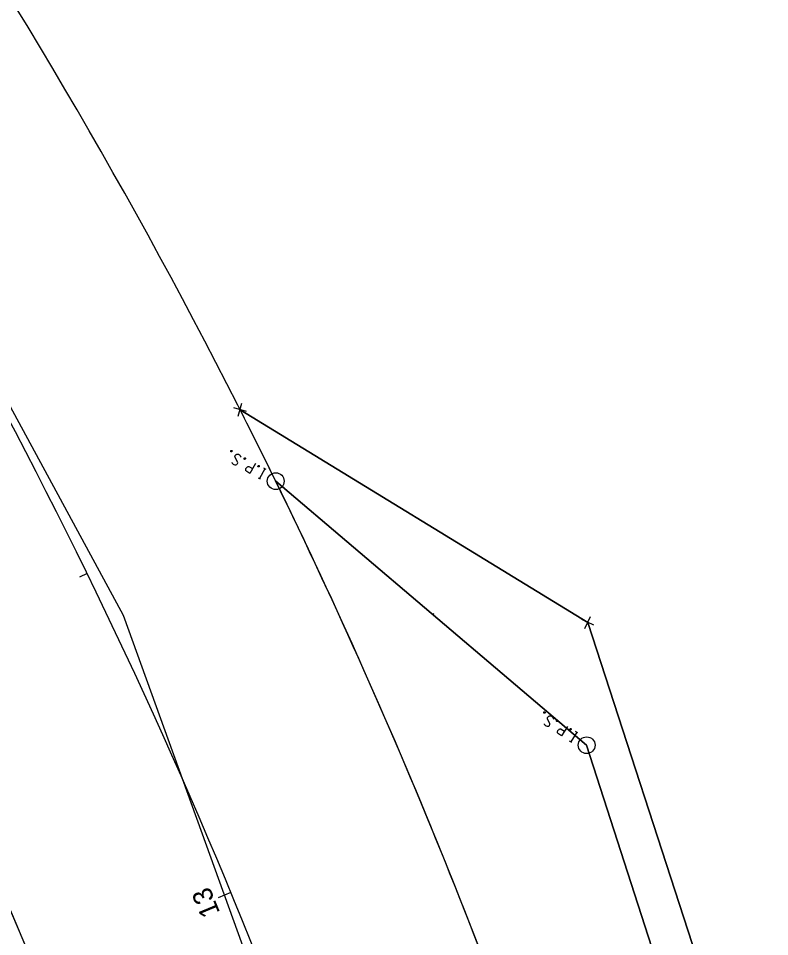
# Model space of a CAD drawing. Extents: x 2392034 to 2394211, y 184331 to 186655.
# Drawn here: x 2392791 to 2392898.3, y 185380.6 to 185511.7 of the extents above; entities that cross this region are included whole.
import ezdxf

# ---------------------------------------------------------------- set-up
doc = ezdxf.new("R2010")
doc.units = 0
for name, color, linetype in [('V-ROAD-SIGN', 7, 'Continuous'), ('V-SITE-MAIL', 7, 'Continuous'), ('V-SURV-ANNO', 7, 'Continuous'), ('V-TOPO-ANNO', 7, 'Continuous'), ('V-TOPO-TINN', 7, 'Continuous'), ('V-TOPO-USER', 7, 'Continuous'), ('V-TOPO-WSHD', 7, 'Continuous'), ('V-UTIL-NGAS-STRC', 7, 'Continuous'), ('V-UTIL-SSWR-STRC', 7, 'Continuous'), ('V-UTIL-STRM-STRC', 7, 'Continuous')]:
    doc.layers.add(name, color=color, linetype=linetype)

msp = doc.modelspace()

# ---------------------------------------------------------------- linework, layer by layer
at = {"layer": 'Defpoints'}
msp.add_circle((2392850.29, 185426.65), 0.05, dxfattribs=at)
at = {"layer": 'V-ROAD-SIGN'}
for radius, end in [(830, 45.41914), (770, 44.49359)]:
    msp.add_arc((2392082.2, 185080.9), radius, 15.02013, end, dxfattribs=at)
at = {"layer": 'V-SITE-MAIL'}
msp.add_arc((2392082.2, 185080.9), 800, 15.02013, 44.49359, dxfattribs=at)
at = {"layer": 'V-SURV-ANNO'}
for p, q in [((2392800.83, 185432.43), (2392799.75, 185431.91)), ((2392821.38, 185386.86), (2392819.54, 185386.1))]:
    msp.add_line(p, q, dxfattribs=at)
at = {"layer": 'V-TOPO-ANNO'}
for p, q in [((2392806.01, 185426.43), (2392759.81, 185511.73)), ((2392806.01, 185426.43), (2392759.81, 185511.73)), ((2392843.3, 185323.45), (2392806.01, 185426.43)), ((2392843.3, 185323.45), (2392806.01, 185426.43))]:
    msp.add_line(p, q, dxfattribs=at)
at = {"layer": 'V-TOPO-TINN'}
for points in [[(2392821.42, 185449.8), (2392821.38, 185449.82), (2392821.36, 185449.86), (2392821.35, 185449.92), (2392821.38, 185449.98), (2392821.44, 185450), (2392821.48, 185450.01), (2392821.53, 185449.98), (2392821.54, 185449.95), (2392821.55, 185449.89), (2392821.52, 185449.83), (2392821.46, 185449.8), (2392821.42, 185449.8)], [(2392821.52, 185448.29), (2392821.53, 185448.26), (2392821.55, 185448.22), (2392821.61, 185448.14), (2392821.71, 185448.06), (2392821.79, 185448.01), (2392821.81, 185448), (2392821.96, 185447.96), (2392822.1, 185447.97), (2392822.22, 185448.02), (2392822.29, 185448.1), (2392822.32, 185448.16), (2392822.35, 185448.26), (2392822.32, 185448.38), (2392821.97, 185449.01), (2392821.94, 185449.08), (2392821.95, 185449.13), (2392821.97, 185449.21), (2392822, 185449.27), (2392822.05, 185449.33), (2392822.08, 185449.37), (2392822.13, 185449.42), (2392822.18, 185449.45), (2392822.22, 185449.47), (2392822.26, 185449.49), (2392822.3, 185449.5), (2392822.35, 185449.5), (2392822.39, 185449.49), (2392822.48, 185449.46), (2392822.62, 185449.38), (2392822.69, 185449.31), (2392822.77, 185449.16), (2392822.82, 185449.06)], [(2392823.33, 185448.74), (2392823.29, 185448.77), (2392823.27, 185448.8), (2392823.26, 185448.86), (2392823.29, 185448.92), (2392823.35, 185448.95), (2392823.39, 185448.95), (2392823.44, 185448.93), (2392823.45, 185448.89), (2392823.46, 185448.83), (2392823.43, 185448.77), (2392823.37, 185448.75), (2392823.33, 185448.74)], [(2392824.87, 185448.13), (2392824.1, 185446.73), (2392823.64, 185446.99), (2392823.6, 185447.03), (2392823.54, 185447.09), (2392823.52, 185447.12), (2392823.51, 185447.16), (2392823.5, 185447.24), (2392823.5, 185447.31), (2392823.53, 185447.41), (2392823.6, 185447.54), (2392823.64, 185447.58), (2392823.69, 185447.64), (2392823.77, 185447.69), (2392823.83, 185447.7), (2392823.87, 185447.71), (2392823.93, 185447.7), (2392824.02, 185447.67), (2392824.48, 185447.42)], [(2392825.3, 185447.65), (2392825.25, 185447.68), (2392825.24, 185447.72), (2392825.23, 185447.78), (2392825.26, 185447.83), (2392825.32, 185447.86), (2392825.36, 185447.87), (2392825.41, 185447.84), (2392825.42, 185447.8), (2392825.43, 185447.74), (2392825.4, 185447.69), (2392825.34, 185447.66), (2392825.3, 185447.65)], [(2392826.24, 185447.38), (2392825.47, 185445.98)], [(2392826.4, 185447.29), (2392826.09, 185447.46)], [(2392825.62, 185445.89), (2392825.32, 185446.06)], [(2392866.12, 185412.47), (2392866.07, 185412.5), (2392866.06, 185412.53), (2392866.06, 185412.59), (2392866.09, 185412.65), (2392866.15, 185412.67), (2392866.19, 185412.68), (2392866.24, 185412.65), (2392866.25, 185412.61), (2392866.25, 185412.55), (2392866.22, 185412.49), (2392866.16, 185412.47), (2392866.12, 185412.47)], [(2392866.12, 185410.95), (2392866.13, 185410.92), (2392866.14, 185410.88), (2392866.21, 185410.8), (2392866.3, 185410.71), (2392866.37, 185410.66), (2392866.4, 185410.65), (2392866.54, 185410.6), (2392866.68, 185410.6), (2392866.8, 185410.64), (2392866.87, 185410.72), (2392866.91, 185410.78), (2392866.95, 185410.88), (2392866.92, 185411), (2392866.62, 185411.64), (2392866.6, 185411.71), (2392866.6, 185411.77), (2392866.63, 185411.84), (2392866.67, 185411.91), (2392866.72, 185411.97), (2392866.75, 185412), (2392866.81, 185412.04), (2392866.85, 185412.07), (2392866.89, 185412.09), (2392866.94, 185412.11), (2392866.98, 185412.11), (2392867.03, 185412.11), (2392867.07, 185412.1), (2392867.16, 185412.06), (2392867.29, 185411.98), (2392867.36, 185411.9), (2392867.43, 185411.75), (2392867.46, 185411.64)], [(2392867.96, 185411.29), (2392867.91, 185411.32), (2392867.9, 185411.36), (2392867.9, 185411.42), (2392867.93, 185411.48), (2392867.99, 185411.5), (2392868.03, 185411.5), (2392868.08, 185411.47), (2392868.09, 185411.43), (2392868.09, 185411.37), (2392868.06, 185411.32), (2392868, 185411.3), (2392867.96, 185411.29)], [(2392869.46, 185410.59), (2392868.6, 185409.24), (2392868.16, 185409.53), (2392868.12, 185409.57), (2392868.06, 185409.63), (2392868.05, 185409.67), (2392868.04, 185409.71), (2392868.03, 185409.78), (2392868.04, 185409.85), (2392868.07, 185409.95), (2392868.15, 185410.08), (2392868.19, 185410.12), (2392868.25, 185410.17), (2392868.33, 185410.22), (2392868.39, 185410.23), (2392868.43, 185410.23), (2392868.49, 185410.22), (2392868.57, 185410.18), (2392869.02, 185409.9)], [(2392869.86, 185410.08), (2392869.81, 185410.11), (2392869.8, 185410.15), (2392869.8, 185410.21), (2392869.83, 185410.27), (2392869.88, 185410.29), (2392869.93, 185410.29), (2392869.97, 185410.26), (2392869.99, 185410.23), (2392869.99, 185410.17), (2392869.95, 185410.11), (2392869.9, 185410.09), (2392869.86, 185410.08)], [(2392870.78, 185409.75), (2392869.92, 185408.4)], [(2392870.93, 185409.65), (2392870.63, 185409.84)], [(2392870.07, 185408.31), (2392869.77, 185408.5)]]:
    msp.add_lwpolyline(points, dxfattribs=at)
for centre in [(2392827.78, 185445.62), (2392872.2, 185407.9)]:
    msp.add_circle(centre, 1.2, dxfattribs=at)
at = {"layer": 'V-TOPO-USER'}
for p, q in [((2392872.2, 185407.9), (2392827.78, 185445.62)), ((2392893.01, 185343.48), (2392872.2, 185407.9))]:
    msp.add_line(p, q, dxfattribs=at)
at = {"layer": 'V-TOPO-WSHD'}
for p, q in [((2392872.35, 185425.45), (2392822.69, 185455.83)), ((2392898.34, 185345.63), (2392872.35, 185425.45))]:
    msp.add_line(p, q, dxfattribs=at)
at = {"layer": 'V-UTIL-NGAS-STRC'}
for p, q in [((2392822.43, 185454.93), (2392822.96, 185456.74)), ((2392823.6, 185455.56), (2392821.79, 185456.1)), ((2392871.95, 185424.59), (2392872.75, 185426.3)), ((2392873.21, 185425.05), (2392871.49, 185425.85))]:
    msp.add_line(p, q, dxfattribs=at)
at = {"layer": 'V-UTIL-SSWR-STRC'}
for p, q in [((2392822.69, 185455.83), (2392872.35, 185425.45)), ((2392872.2, 185407.9), (2392827.78, 185445.62)), ((2392872.2, 185407.9), (2392827.78, 185445.62)), ((2392872.35, 185425.45), (2392898.34, 185345.63)), ((2392893.01, 185343.48), (2392872.2, 185407.9)), ((2392893.01, 185343.48), (2392872.2, 185407.9))]:
    msp.add_line(p, q, dxfattribs=at)
msp.add_arc((2392082.2, 185080.9), 830, 17.83729, 26.06673, dxfattribs=at)
at = {"layer": 'V-UTIL-STRM-STRC'}
for p, q in [((2392872.35, 185425.45), (2392822.69, 185455.83)), ((2392827.78, 185445.62), (2392872.2, 185407.9)), ((2392827.78, 185445.62), (2392872.2, 185407.9)), ((2392898.34, 185345.63), (2392872.35, 185425.45)), ((2392872.2, 185407.9), (2392893.01, 185343.48)), ((2392872.2, 185407.9), (2392893.01, 185343.48))]:
    msp.add_line(p, q, dxfattribs=at)
for radius, start, end in [(770, 16.39806, 33.9449), (830, 26.06673, 26.85454), (830, 26.06673, 26.85454), (830, 26.06673, 26.85454), (830, 17.83729, 26.06673)]:
    msp.add_arc((2392082.2, 185080.9), radius, start, end, dxfattribs=at)

# ---------------------------------------------------------------- texts
at = {"layer": 'V-SURV-ANNO'}
msp.add_text('13', height=2.8, rotation=112.4857, dxfattribs=at).set_placement((2392819.87, 185383.98))

doc.saveas('drawing.dxf')
